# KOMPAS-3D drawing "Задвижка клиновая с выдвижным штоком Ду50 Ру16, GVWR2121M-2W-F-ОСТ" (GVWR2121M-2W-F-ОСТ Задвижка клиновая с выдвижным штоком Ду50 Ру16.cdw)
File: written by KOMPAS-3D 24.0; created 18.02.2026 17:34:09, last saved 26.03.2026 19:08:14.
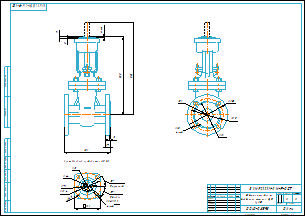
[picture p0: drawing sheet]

Document properties: Автор: R2D2; Форматы листов документа: A2; Полное имя файла: GVWR2121M-2W-F-ОСТ Задвижка клиновая с выдвижным штоком Ду50 Ру16.m3d; Масса: 12; Наименование: Задвижка клиновая с выдвижным штоком Ду50 Ру16; Количество листов документа: 1; Примечание: D040-08598

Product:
- Part/product: Задвижка клиновая с выдвижным штоком Ду50 Ру16  | designation GVWR2121M-2W-F-ОСТ
    Масса: 12
    Раздел спецификации: Прочие изделия
    Примечание: D040-08598

Views: Проекционный вид 3
Referenced files in E:\Работа\Зайцев\Для компаса\: чертеж DN.ru А3.cdt
Referenced files in E:\Работа\Зайцев\GVWR2121M-2W-F-ОСТ Задвижка клиновая с видвижным штоком Ду50-300 Ру16\DN50\: GVWR2121M-2W-F-ОСТ Задвижка клиновая с выдвижным штоком Ду50 Ру16.m3d
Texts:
  Присоединение привода тип АК (А)
  чертеж DN.ru А3.cdt
  Задвижка клиновая с
  выдвижным штоком Ду50
  Ру16
  GVWR2121M-2W-F-ОСТ
  Задвижка клиновая с выдвижным штоком Ду50 Ру16
  GVWR2121M-2W-F-ОСТ Задвижка клиновая с выдвижным штоком Ду50 Ру16
Dimensions and other numbers on the sheet: 100; 5 кулачков; 5 впадин; 14 (М12); 4 отв.; 13,5; 104; 70; 44; 32; 1:2; 0; 1; 2; 12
